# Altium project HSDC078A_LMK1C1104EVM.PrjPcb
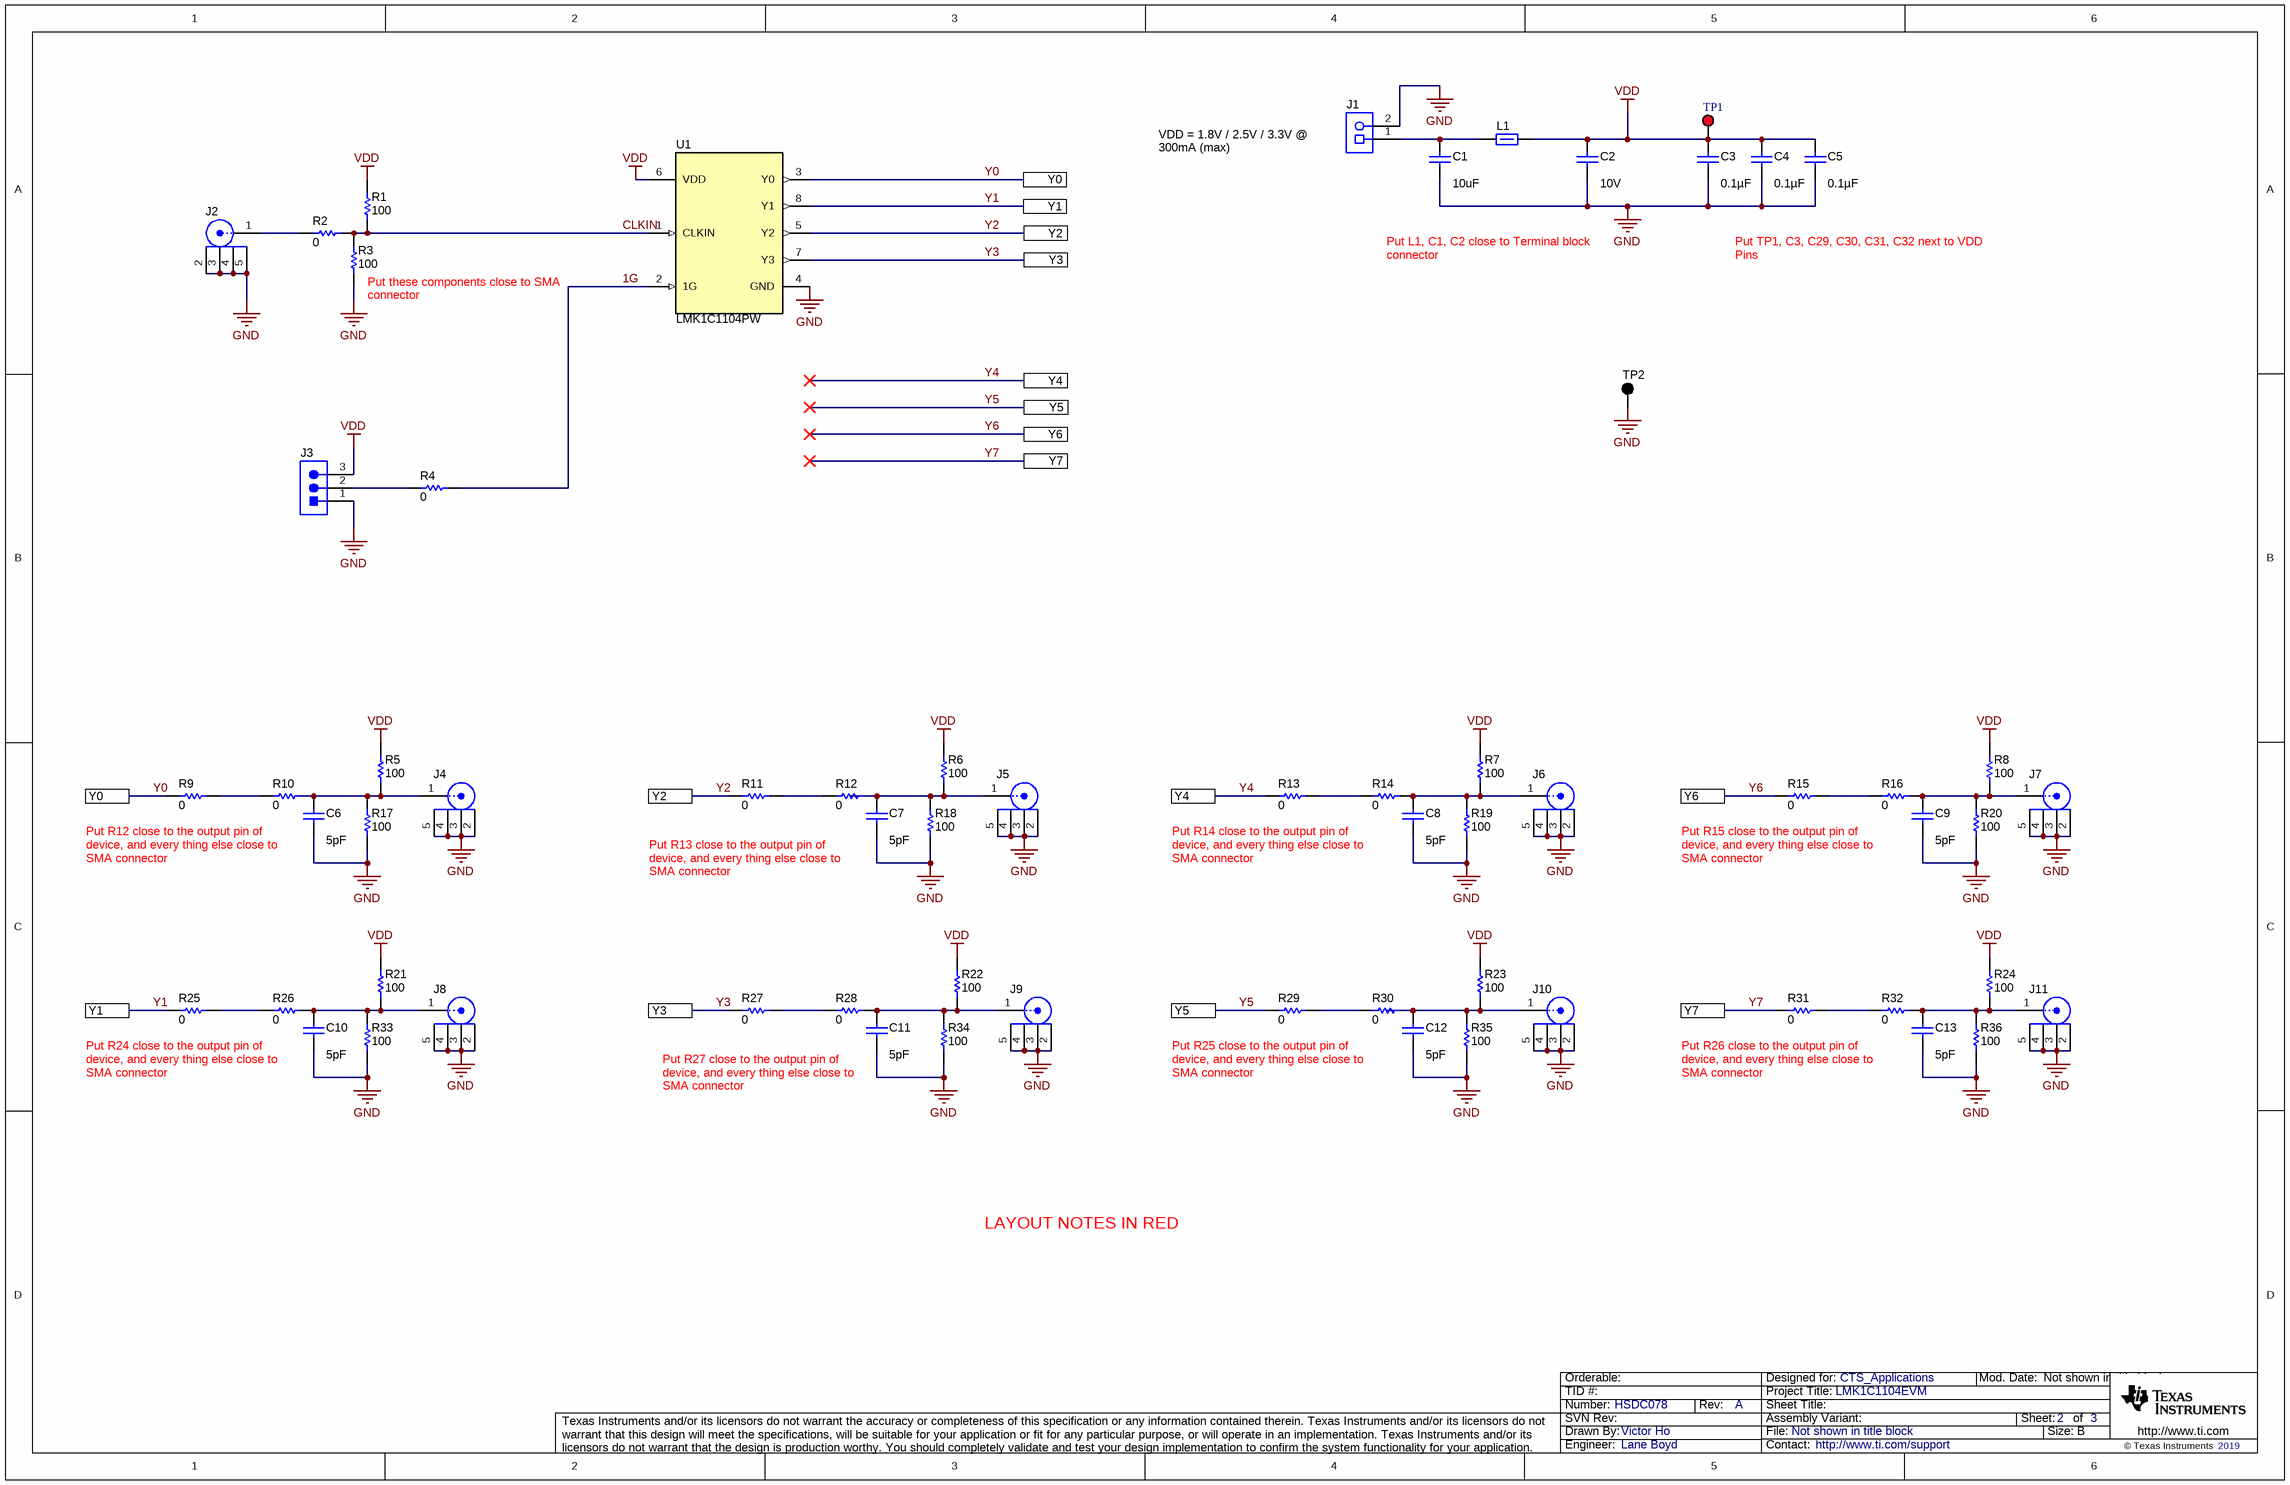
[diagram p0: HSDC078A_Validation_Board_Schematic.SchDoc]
CopyrightYear: 2019; PCB_Layout: Krypton; PCB_Rev: A; PRJ_Customer: CTS_Applications; PRJ_Engineer: Lane Boyd; PRJ_Number: HSDC078; PRJ_Title: LMK1C1104EVM; SCH_Rev: A; TechSupport: http://www.ti.com/support
2 sheets, 84 parts. Net scope: flat (ports and power ports of the same name join across sheets).
Board file: HSDC078A_Validation_Board_PCB.PcbDoc
Sheets:
  HSDC078A_Validation_Board_Schematic.SchDoc
  HSDC078A_Hardware.SchDoc

## Sheet HSDC078A_Validation_Board_Schematic.SchDoc
size 431 x 279 mm; Date: Not shown in title block; ApprovedBy: Not shown in title block; CheckedBy: Not shown in title block; Author: Not shown in title block; CompanyName: Not shown in title block; DrawnBy: Victor Ho; Engineer: Victor Ho; Organization: Not shown in title block; Address1: Not shown in title block; Address2: Not shown in title block; Address3: Not shown in title block; Address4: Not shown in title block; DocumentNumber: 2; Revision: Use project parameter SCH_Rev; SheetNumber: 2; SheetTotal: 3; PageSetup: Record=PageOptions¦CenterHorizontal=True¦CenterVertical=True¦PrintScale=1.00¦XCorrection=1.00¦YCorrection=1.00¦PrintKind=0¦BorderSize=5000000¦LeftOffset=0¦BottomOffset=0¦Orientation=2¦PaperLength=1000¦PaperWidth=1000¦Scale=100¦PaperSource=15¦PrintQuality=600¦MediaType=1¦DitherType=10¦PaperKind=Letter¦PrintScaleMode=1

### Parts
C1  ValueDisplayed: 10uF  [0805_HV]  (hidden comment: C0805C106K8PACTU)
C2  VDC_V: 10V  [0603]  (hidden comment: C0603X105J8RAC7867)
C3  ValueDisplayed: 0.1µF  [0402]  (hidden comment: C0402C104K8RACAUTO)
C4  ValueDisplayed: 0.1µF  [0402]  (hidden comment: C0402C104K8RACAUTO)
C5  ValueDisplayed: 0.1µF  [0402]  (hidden comment: C0402C104K8RACAUTO)
C6  ValueDisplayed: 5pF  [0603]  (hidden comment: GRM1885C2A5R0CA01D)
C7  ValueDisplayed: 5pF  [0603]  (hidden comment: GRM1885C2A5R0CA01D)
C8  ValueDisplayed: 5pF  [0603]  (hidden comment: GRM1885C2A5R0CA01D)
C9  ValueDisplayed: 5pF  [0603]  (hidden comment: GRM1885C2A5R0CA01D)
C10  ValueDisplayed: 5pF  [0603]  (hidden comment: GRM1885C2A5R0CA01D)
C11  ValueDisplayed: 5pF  [0603]  (hidden comment: GRM1885C2A5R0CA01D)
C12  ValueDisplayed: 5pF  [0603]  (hidden comment: GRM1885C2A5R0CA01D)
C13  ValueDisplayed: 5pF  [0603]  (hidden comment: GRM1885C2A5R0CA01D)
J1  039544-3002  [Molex_039544-3002]  (value not drawn)
J2  CON-SMA-EDGE-S  [FP-SMA-EDGE-S-CUSTOM]  (value not drawn)
J3  PBC03SAAN  [PBC03SAAN]  (value not drawn)
J4  CON-SMA-EDGE-S  [FP-SMA-EDGE-S-CUSTOM]  (value not drawn)
J5  CON-SMA-EDGE-S  [FP-SMA-EDGE-S-CUSTOM]  (value not drawn)
J6  CON-SMA-EDGE-S  [FP-SMA-EDGE-S-CUSTOM]  (value not drawn)
J7  CON-SMA-EDGE-S  [FP-SMA-EDGE-S-CUSTOM]  (value not drawn)
J8  CON-SMA-EDGE-S  [FP-SMA-EDGE-S-CUSTOM]  (value not drawn)
J9  CON-SMA-EDGE-S  [FP-SMA-EDGE-S-CUSTOM]  (value not drawn)
J10  CON-SMA-EDGE-S  [FP-SMA-EDGE-S-CUSTOM]  (value not drawn)
J11  CON-SMA-EDGE-S  [FP-SMA-EDGE-S-CUSTOM]  (value not drawn)
L1  BLM31SN500SZ1L  [1206]  (value not drawn)
R1  ValueDisplayed: 100  [0603]  (hidden comment: CRCW0603100RFKEA)
R2  ValueDisplayed: 0  [0603]  (hidden comment: RC0603JR-070RL)
R3  ValueDisplayed: 100  [0603]  (hidden comment: CRCW0603100RFKEA)
R4  ValueDisplayed: 0  [0603]  (hidden comment: RC0603JR-070RL)
R5  ValueDisplayed: 100  [0603]  (hidden comment: CRCW0603100RFKEA)
R6  ValueDisplayed: 100  [0603]  (hidden comment: CRCW0603100RFKEA)
R7  ValueDisplayed: 100  [0603]  (hidden comment: CRCW0603100RFKEA)
R8  ValueDisplayed: 100  [0603]  (hidden comment: CRCW0603100RFKEA)
R9  ValueDisplayed: 0  [0603]  (hidden comment: RC0603JR-070RL)
R10  ValueDisplayed: 0  [0603]  (hidden comment: RC0603JR-070RL)
R11  ValueDisplayed: 0  [0603]  (hidden comment: RC0603JR-070RL)
R12  ValueDisplayed: 0  [0603]  (hidden comment: RC0603JR-070RL)
R13  ValueDisplayed: 0  [0603]  (hidden comment: RC0603JR-070RL)
R14  ValueDisplayed: 0  [0603]  (hidden comment: RC0603JR-070RL)
R15  ValueDisplayed: 0  [0603]  (hidden comment: RC0603JR-070RL)
R16  ValueDisplayed: 0  [0603]  (hidden comment: RC0603JR-070RL)
R17  ValueDisplayed: 100  [0603]  (hidden comment: CRCW0603100RFKEA)
R18  ValueDisplayed: 100  [0603]  (hidden comment: CRCW0603100RFKEA)
R19  ValueDisplayed: 100  [0603]  (hidden comment: CRCW0603100RFKEA)
R20  ValueDisplayed: 100  [0603]  (hidden comment: CRCW0603100RFKEA)
R21  ValueDisplayed: 100  [0603]  (hidden comment: CRCW0603100RFKEA)
R22  ValueDisplayed: 100  [0603]  (hidden comment: CRCW0603100RFKEA)
R23  ValueDisplayed: 100  [0603]  (hidden comment: CRCW0603100RFKEA)
R24  ValueDisplayed: 100  [0603]  (hidden comment: CRCW0603100RFKEA)
R25  ValueDisplayed: 0  [0603]  (hidden comment: RC0603JR-070RL)
R26  ValueDisplayed: 0  [0603]  (hidden comment: RC0603JR-070RL)
R27  ValueDisplayed: 0  [0603]  (hidden comment: RC0603JR-070RL)
R28  ValueDisplayed: 0  [0603]  (hidden comment: RC0603JR-070RL)
R29  ValueDisplayed: 0  [0603]  (hidden comment: RC0603JR-070RL)
R30  ValueDisplayed: 0  [0603]  (hidden comment: RC0603JR-070RL)
R31  ValueDisplayed: 0  [0603]  (hidden comment: RC0603JR-070RL)
R32  ValueDisplayed: 0  [0603]  (hidden comment: RC0603JR-070RL)
R33  ValueDisplayed: 100  [0603]  (hidden comment: CRCW0603100RFKEA)
R34  ValueDisplayed: 100  [0603]  (hidden comment: CRCW0603100RFKEA)
R35  ValueDisplayed: 100  [0603]  (hidden comment: CRCW0603100RFKEA)
R36  ValueDisplayed: 100  [0603]  (hidden comment: CRCW0603100RFKEA)
TP1  5000  [Keystone5000]  (value not drawn)
TP2  5001  [Keystone5001]  (value not drawn)
U1  LMK1C1104PW  [PW0008A_N]

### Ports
Y0, Y1, Y2, Y3, Y4, Y5, Y6, Y7

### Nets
GND: C1.2 C2.2 C3.1 C4.1 C5.1 C6.2 C7.2 C8.2 C9.2 C10.2 C11.2 C12.2 C13.2 J1.2 J2.2 J2.3 J2.4 J2.5 J3.1 J4.2 J4.3 J4.4 J4.5 J5.2 J5.3 J5.4 J5.5 J6.2 J6.3 J6.4 J6.5 J7.2 J7.3 J7.4 J7.5 J8.2 J8.3 J8.4 J8.5 J9.2 J9.3 J9.4 J9.5 J10.2 J10.3 J10.4 J10.5 J11.2 J11.3 J11.4 J11.5 R3.2 R17.2 R18.2 R19.2 R20.2 R33.2 R34.2 R35.2 R36.2 TP2.1 U1.4(GND)
VDD: C2.1 C3.2 C4.2 C5.2 J3.3 L1.2 R1.1 R5.2 R6.2 R7.2 R8.2 R21.2 R22.2 R23.2 R24.2 TP1.1 U1.6(VDD)
1G: R4.1 U1.2(1G)
CLKIN: R1.2 R2.2 R3.1 U1.1(CLKIN)
Y0: R9.1 U1.3(Y0) ; port Y0
Y1: R25.1 U1.8(Y1) ; port Y1
Y2: R11.1 U1.5(Y2) ; port Y2
Y3: R27.1 U1.7(Y3) ; port Y3
Y4: R13.1 ; port Y4
Y5: R29.1 ; port Y5
Y6: R15.1 ; port Y6
Y7: R31.1 ; port Y7
NetC1_1: C1.1 J1.1 L1.1
NetC6_1: C6.1 J4.1 R5.1 R10.2 R17.1
NetC7_1: C7.1 J5.1 R6.1 R12.2 R18.1
NetC8_1: C8.1 J6.1 R7.1 R14.2 R19.1
NetC9_1: C9.1 J7.1 R8.1 R16.2 R20.1
NetC10_1: C10.1 J8.1 R21.1 R26.2 R33.1
NetC11_1: C11.1 J9.1 R22.1 R28.2 R34.1
NetC12_1: C12.1 J10.1 R23.1 R30.2 R35.1
NetC13_1: C13.1 J11.1 R24.1 R32.2 R36.1
NetJ2_1: J2.1 R2.1
NetJ3_2: J3.2 R4.2
NetR9_2: R9.2 R10.1
NetR11_2: R11.2 R12.1
NetR13_2: R13.2 R14.1
NetR15_2: R15.2 R16.1
NetR25_2: R25.2 R26.1
NetR27_2: R27.2 R28.1
NetR29_2: R29.2 R30.1
NetR31_2: R31.2 R32.1

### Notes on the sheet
- VDD = 1.8V / 2.5V / 3.3V @ 300mA (max)
- (near R3) Put these components close to SMA connector
- Put L1, C1, C2 close to Terminal block connector
- Put TP1, C3, C29, C30, C31, C32 next to VDD Pins
- Put R12 close to the output pin of device, and every thing else close to SMA connector
- Put R13 close to the output pin of device, and every thing else close to SMA connector
- Put R14 close to the output pin of device, and every thing else close to SMA connector
- Put R15 close to the output pin of device, and every thing else close to SMA connector
- Put R24 close to the output pin of device, and every thing else close to SMA connector
- (near C11) Put R27 close to the output pin of device, and every thing else close to SMA connector
- Put R25 close to the output pin of device, and every thing else close to SMA connector
- Put R26 close to the output pin of device, and every thing else close to SMA connector
- LAYOUT NOTES IN RED

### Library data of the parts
C1 = CMP-0007732-1: CAP, CERM, 10 uF, 10 V, +/- 10%, X5R, 0805; Manufacturer: Kemet; TaMin_C: -55°C; ESR_ohm: 3m; Polarized: N; SizeAreaWB_mm2: 6.75; Value1: 0.003 ohm; U/M: EA; Value: 10uF; TaMax_C: 85°C; SizeZ_mm: 1.45; SizeX_mm: 2; SizeY_mm: 1.25; Cap_Case: 0805; Value2: 10V; SizeArea_mm2: 2.5; Cap_F: 10µF; IRMS_A: 11.43A; AEC Category: Q200
C2 = CMP-0084112-1: CAP, CERM, 1 µF, 10 V,+/- 5%, X7R, AEC-Q200 Grade 1, 0603; Manufacturer: Kemet; Cap_F: 1µF; SizeAreaWB_mm2: 4.68; SizeArea_mm2: 1.28; AEC Qualified: Y; AEC Category: Q200; Value: 1uF; TaMax_C: 125°C; SizeZ_mm: 1; Polarized: N; TaMin_C: -55°C; SizeY_mm: 0.8; U/M: EA; SizeX_mm: 1.6
C3-C5 = CMP-0079150-1: CAP, CERM, 0.1 µF, 10 V,+/- 10%, X7R, AEC-Q200 Grade 1, 0402; Manufacturer: Kemet; Cap_F: 100nF; SizeAreaWB_mm2: 3; SizeArea_mm2: 0.5; AEC Qualified: Y; AEC Category: Q200; Value: 0.1uF; TaMax_C: 125°C; SizeZ_mm: 0.6; AEC Grade: 1; Polarized: N; TaMin_C: -55°C; VDC_V: 10V; U/M: EA
C6-C13 = CMP-0007277-4: CAP, CERM, 5 pF, 100 V, +/- 5%, C0G/NP0, 0603; Manufacturer: MuRata; TaMin_C: -55°C; Polarized: N; SizeAreaWB_mm2: 4.68; Value1: Unknown; U/M: EA; Value: 5pF; TaMax_C: 125°C; SizeZ_mm: 1; SizeX_mm: 1.6; SizeY_mm: 0.8; Value2: 100V; SizeArea_mm2: 1.28; AEC Category: Q200
J1 = CMP-0055345-1: Terminal Block, 5.08mm, 2x1, TH; Manufacturer: Molex; CNHeader: FALSE; Current_A: 15A; Gender: Female; Voltage_V: 300V; Row_Count: 1; Pitch_mm: 5.08; ContactFinish: Tin; CT: TRUE; Cert_UL: Y
J2 J4-J11 = CMP-0088000-4: CONN SMA JACK STR EDGE MNT; Manufacturer: RF Solutions Ltd.; ContactFinish: Gold; Shrouded: true
J3 = CMP-0002334-1: Header, 100mil, 3x1, Gold, TH; Manufacturer: Sullins Connector Solutions; CNHeader: TRUE; Green_Lifecycle: Not Set; Green_REACh: Incomplete; CT: FALSE
L1 = CMP-0003368-1: Ferrite Bead, 50 ohm @ 100 MHz, 12 A, 1206; Manufacturer: MuRata; ZTyp@100MHz_Ohm: 50; SizeAreaWB_mm2: 10.92; DCR_ohm: 1.6m; Value1: 0.0016 ohm; Value: 50 ohm; Imax_A: 12A; SizeZ_mm: 1.35; SizeX_mm: 3.2; SizeY_mm: 1.6; SizeArea_mm2: 5.12
R1 R3 R5-R8 R17-R24 R33-R36 = CMP-0021991-4: RES, 100, 1%, 0.1 W, AEC-Q200 Grade 0, 0603; Manufacturer: Vishay-Dale; Power_W: 100mW; TempCo: 100 ppm/C; Value_Code: 100R; Value: 100; EIA_Code: E96; SizeX_mm: 1.6; SizeY_mm: 0.8; SizeZ_mm: 1; Value2: 0.1W; SizeArea_mm2: 1.28; AEC Qualified: Y; VDC_V: 75V; AEC Category: Q200; AEC Grade: 0
R2 R4 R9-R16 R25-R32 = CMP-0025885-5: RES, 0, 5%, 0.1 W, 0603; Manufacturer: Yageo; Power_W: 100mW; TempCo: 200 ppm/C; Value_Code: 0000; Value: 0; EIA_Code: E24; SizeX_mm: 1.6; SizeZ_mm: 1; Value2: 0.1W; SizeArea_mm2: 1.28; AEC Qualified: N; VDC_V: 75V; AEC Category: Q200; SizeY_mm: 0.8; SizeAreaWB_mm2: 4.68
TP1 = CMP-0055137-1: Test Point, Miniature, Red, TH; Manufacturer: Keystone; CNHeader: FALSE; Green_Lifecycle: Active; Green_REACh: Passed; ContactFinish: Silver; CT: TRUE
TP2 = CMP-0055138-1: Test Point, Miniature, Black, TH; Manufacturer: Keystone; CNHeader: FALSE; Green_Lifecycle: Active; Green_REACh: Passed; ContactFinish: Silver; CT: TRUE
U1 = CMP-0860874-2: 3.3-V and 2.5-V LVCMOS High-Performance Clock Buffer Family, PW0008A (TSSOP-8); Alternate PartNumber: LMK1C1104PWR; Manufacturer: Texas Instruments; AEC Qualified: N; SizeZ_mm: 1.2; SizeY_mm: 3; SizeArea_mm2: 19.2; CompType: IC; SizeX_mm: 6.4; SizeAreaWB_mm2: 42; AEC Category: Q200

## Sheet HSDC078A_Hardware.SchDoc
size 431 x 279 mm; Date: Not shown in title block; ApprovedBy: Not shown in title block; CheckedBy: Not shown in title block; Author: Not shown in title block; CompanyName: Not shown in title block; Engineer: Not shown in title block; Organization: Not shown in title block; Address1: Not shown in title block; Address2: Not shown in title block; Address3: Not shown in title block; Address4: Not shown in title block; DocumentNumber: 3; Revision: Use project parameter SCH_Rev; SheetNumber: 3; SheetTotal: 3; PageSetup: Record=PageOptions¦CenterHorizontal=True¦CenterVertical=True¦PrintScale=1.00¦XCorrection=1.00¦YCorrection=1.00¦PrintKind=0¦BorderSize=5000000¦LeftOffset=0¦BottomOffset=0¦Orientation=2¦PaperLength=1000¦PaperWidth=1000¦Scale=100¦PaperSource=15¦PrintQuality=600¦MediaType=1¦DitherType=10¦PaperKind=Letter¦PrintScaleMode=1
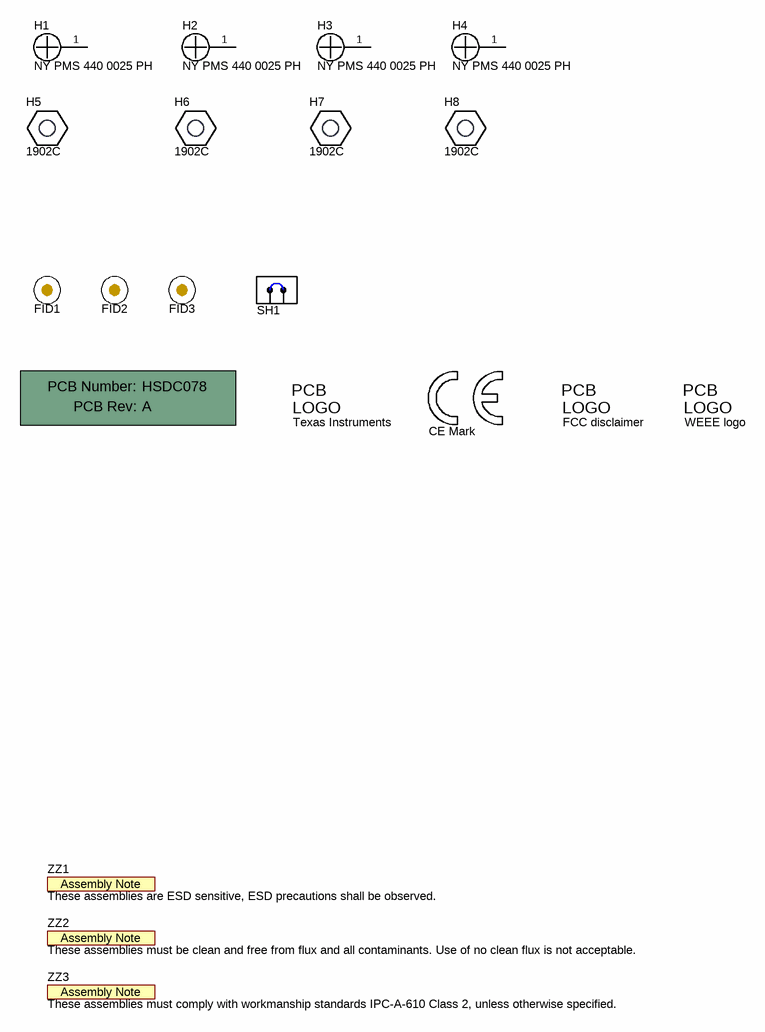
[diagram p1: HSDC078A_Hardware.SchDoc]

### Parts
!PCB1  Printed Circuit Board  (value not drawn)  (mechanical)
FID1  Fiducial  [Fiducial10-20]  (value not drawn)
FID2  Fiducial  [Fiducial10-20]  (value not drawn)
FID3  Fiducial  [Fiducial10-20]  (value not drawn)
H1  NY PMS 440 0025 PH  [NY PMS 440 0025 PH]
H2  NY PMS 440 0025 PH  [NY PMS 440 0025 PH]
H3  NY PMS 440 0025 PH  [NY PMS 440 0025 PH]
H4  NY PMS 440 0025 PH  [NY PMS 440 0025 PH]
H5  1902C  [Keystone_1902C]
H6  1902C  [Keystone_1902C]
H7  1902C  [Keystone_1902C]
H8  1902C  [Keystone_1902C]
Logo1  CE Mark  [CE_Mark_5mm]  (no BOM)
Logo2  Texas Instruments  [TI_Stacked_Overlay_Small]  (no BOM)
Logo3  FCC disclaimer  [FCC_disclaimer]  (no BOM)
Logo4  WEEE logo  [WEEE_Minimum]  (no BOM)
SH1  SNT-100-BK-G  [SNT-100-BK-G]  (value not drawn)
ZZ1  These assemblies are ESD sensitive, ESD precautions shall be observed.  [AssemblyNote]  (no BOM)
ZZ2  These assemblies must be clean and free from flux and all contaminants. Use of no clean flux is not acceptable.  [AssemblyNote]  (no BOM)
ZZ3  These assemblies must comply with workmanship standards IPC-A-610 Class 2, unless otherwise specified.  [AssemblyNote]  (no BOM)

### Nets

Not connected (* = marked no-connect by the designer): H1 1; H2 1; H3 1; H4 1

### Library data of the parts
!PCB1 = CMP-0003618-2: Manufacturer: Any; PartNumber: HSDC078; CompType: PCB
FID1-FID3 = CMP-0077181-1: Fiducial mark.  There is nothing to buy or mount.
H1-H4 = CMP-0003617-1: Machine Screw, Round, #4-40 x 1/4, Nylon, Philips panhead; Manufacturer: B&F Fastener Supply; CompType: Hardware
H5-H8 = CMP-0003610-1: Standoff, Hex, 0.5"L #4-40 Nylon; Manufacturer: Keystone; CompType: Hardware
Logo1 = CMP-0074844-1: SymbolCreator: a0412235
Logo2 = CMP-0074838-1: Texas Instrument Corporate Signature; SymbolCreator: a0412235; Lib Reference: TI_Logo; Library Reference: Logo
Logo3 = CMP-0074847-1: FCC_disclaimer; Library Reference: Logo
Logo4 = CMP-0074769-1
SH1 = CMP-0003623-3: Shunt, 100mil, Gold plated, Black; Alternate PartNumber: 969102-0000-DA; Manufacturer: Samtec; Alternate Manufacturer: 3M; Value: 1x2
ZZ1 = CMP-0077236-1
ZZ2 = CMP-0077237-1
ZZ3 = CMP-0077238-1

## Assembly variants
001: not fitted C6 C7 C8 C9 C10 C11 C12 C13 FID1 FID2 FID3 J6 J7 J10 J11 R1 R3 R5 R6 R7 R8 R13 R14 R15 R16 R17 R18 R19 R20 R21 R22 R23 R24 R29 R30 R31 R32 R33 R34 R35 R36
